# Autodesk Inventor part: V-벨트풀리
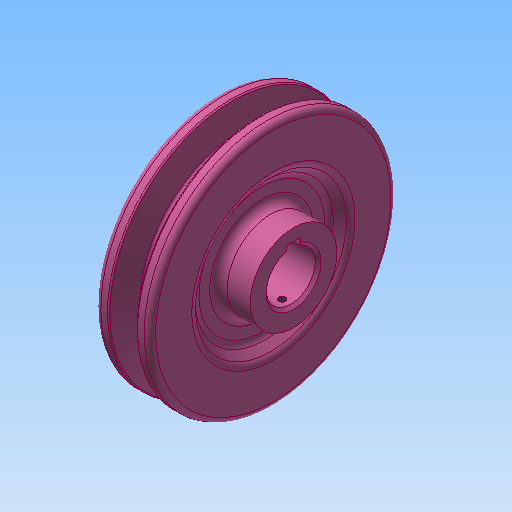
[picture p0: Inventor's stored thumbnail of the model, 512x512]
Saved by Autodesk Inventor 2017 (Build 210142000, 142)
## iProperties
Company: 한국ATC센터
Created: 2015-12
Part Number: V-벨트풀리
Document SubType Name: Modeling
Designer: mdu
Density: 7.25 g/cm^3
Mass: 596.065 g
Surface Area: 214.402 cm^2
Volume: 82.2158 cm^3
Material: 주철
Appearance: 분홍색
Author: mdu
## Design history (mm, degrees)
sketch "스케치1"
  geometry: L1 (-13, 0)-(13, 0); L2 (-13, 0)-(-13, 15); L3 (-13, 15)-(-9, 15); L4 (-9, 15)-(-9, 23); L5 (-9, 23)-(-13, 27); L6 (-13, 27)-(-13, 42.7); L7 (-13, 42.7)-(-8.325, 42.7); L8 (-8.325, 42.7)-(-5.574, 33.7); L9 (-5.574, 33.7)-(-1.426, 33.7); L10 (-1.426, 33.7)-(1.325, 42.7); L11 (1.325, 42.7)-(6, 42.7); L12 (6, 42.7)-(6, 27); L13 (6, 27)-(2, 23); L14 (2, 23)-(2, 15); L15 (2, 15)-(13, 15); L16 (13, 15)-(13, 0); L17 (-7.5, 40)-(0.5, 40); 2 further points
  constraints: 34 end point, 6 parallel, 5 collinear, 5 equal length, 4 perpendicular, 2 point on line, 1 coincident, 1 horizontal, 1 midpoint
  dimensions: "d0" = 26 distance of L1.start L1.end; "d1" = 2.7 distance between parallel lines of L7 L17; "d2" = 6.3 distance between parallel lines of L9 L17; "d3" = 8 distance of L17.start L17.end; "d4" = 34 deg angle of L10 L8; "d5" = 19 distance between parallel lines of L12 L6; "d7" = 30 diameter of L15 L1; "d8" = 46 diameter of L13.end L1; "d9" = 54 diameter of L12.end L1; "d10" = 4 distance between parallel lines of L2 L4; "d11" = 80 diameter of L17 L1
revolve "회전1" sketch "스케치1" stored, may be unused: angle "d12" = 90 deg
sketch "스케치2"
  geometry: L1 (-2.5, 8.124)-(-2.5, 10.8); L2 (-2.5, 10.8)-(2.5, 10.8); L3 (2.5, 10.8)-(2.5, 8.124); A1 r 8.5 centre (0, 0) between (-2.5, 8.124) and (2.5, 8.124); 1 further point
  constraints: 6 end point, 2 parallel, 2 point on circle, 1 centre point, 1 coincident, 1 perpendicular, 1 vertical
  dimensions: "d13" = 17 diameter of A1; "d14" = 19.3 dimension on A1 L2; "d15" = 5 distance of L1.end L2.end
extrude "돌출1" cut sketch "스케치2" stored distance "d16" = 10; taper "d17" = 0 deg
node "작업 평면1"
sketch "스케치3"
  geometry: L1 (-5.5, 15)-(-5.5, -15) reference; L2 (20.5, 27)-(20.5, -27) reference; 3 further points
  constraints: 1 horizontal alignment, 1 midpoint
  dimensions: "d18" = 4 distance from line of point (-1.5, 0) L1; "d33" = 22 distance from line of point (-1.5, 0) L2 (derived)
hole "구멍1" sketch "스케치3" at (-1.5, 0) diameter "d19" = 2.459; stored, may be unused: countersink angle "d23" = 90 deg, drill point angle "d25" = 118 deg; dims "d20" = 6, "d21" = 4, "d22" = 2, "d24" = 8
fillet "모깎기1" dims "d26" = 2, "d27" = 0.5, "d28" = 1, "d29" = 3
chamfer "모따기1" distance "d30" = 1; stored, may be unused: second distance "d31" = 2, angle "d32" = 45 deg
sketch "스케치4" dims "d35" = 70
  geometry: C1 r 2 at (35, 0); 2 further points
  constraints: 2 horizontal alignment, 1 centre point, 1 coincident, 2 other
  dimensions: "d34" = 4 diameter of C1
extrude "돌출2" cut sketch "스케치4" distance "d36" = 1; taper "d37" = 0 deg
fillet "모깎기3" dims "d40" = 0.5
node "솔리드1"
